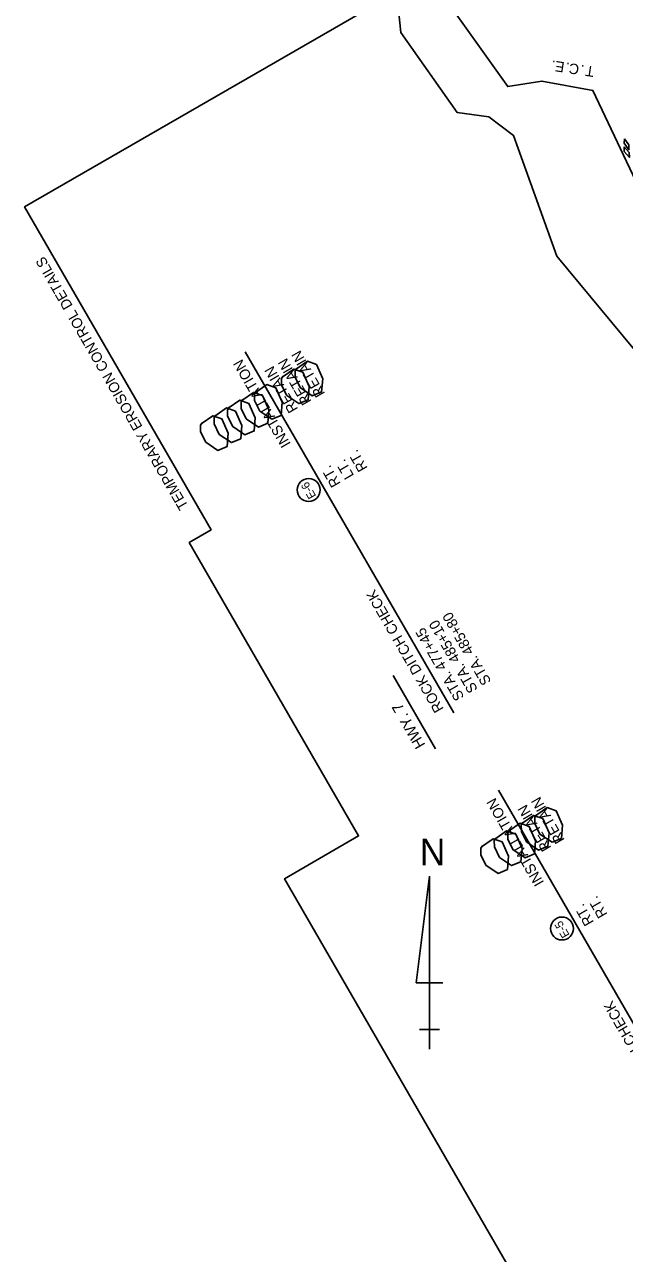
# Model space of a CAD drawing. Extents: x 956270 to 957915, y 1920520 to 1922423.
# Drawn here: x 956270 to 956617, y 1921329 to 1922039 of the extents above; entities that cross this region are included whole.
import ezdxf

# ---------------------------------------------------------------- set-up
doc = ezdxf.new("R2010")
doc.units = 0
for name, color, linetype in [('1', 7, 'Continuous'), ('44', 7, 'Continuous'), ('63', 7, 'Continuous'), ('G-ANNO-SYMB', 7, 'Continuous'), ('NO PLOT', 7, 'Continuous'), ('R_Draft', 7, 'Continuous'), ('S_TREE', 7, 'Continuous')]:
    doc.layers.add(name, color=color, linetype=linetype)

msp = doc.modelspace()

# ---------------------------------------------------------------- linework, layer by layer
at = {"layer": '1'}
for centre in [(956434.43, 1921770.52), (956580.77, 1921517.05)]:
    msp.add_circle(centre, 6.61, dxfattribs=at)
at = {"layer": '44'}
for p, q in [((956518.31, 1921641.7), (956397.8, 1921850.42)), ((956507.68, 1921620.92), (956483.26, 1921663.22)), ((956664.65, 1921388.23), (956544.14, 1921596.95))]:
    msp.add_line(p, q, dxfattribs=at)
at = {"layer": '63'}
for p, q in [((956504.2, 1921547.25), (956496.5, 1921485.71)), ((956504.2, 1921447.25), (956504.2, 1921547.25)), ((956504.2, 1921547.25), (956504.2, 1921470.33)), ((956496.5, 1921485.71), (956511.89, 1921485.71)), ((956504.2, 1921447.25), (956504.2, 1921470.33)), ((956504.2, 1921458.79), (956498.43, 1921458.79)), ((956498.43, 1921458.79), (956509.97, 1921458.79)), ((956504.2, 1921447.25), (956504.2, 1921458.79))]:
    msp.add_line(p, q, dxfattribs=at)
at = {"layer": 'G-ANNO-SYMB'}
for points in [[(956616.88, 1921973.43), (956616.74, 1921970.87), (956619.46, 1921967.19), (956619.44, 1921969.96)], [(956616.71, 1921968.75), (956616.77, 1921966.18), (956619.77, 1921962.73), (956619.54, 1921965.49)]]:
    msp.add_lwpolyline(points, close=True, dxfattribs=at)
at = {"layer": 'NO PLOT'}
msp.add_lwpolyline([(957012.51, 1920520.44), (956420.48, 1921545.87), (956463.26, 1921570.57), (956365.36, 1921740.14), (956378, 1921747.44), (956270.25, 1921934.07), (956666.17, 1922162.65), (956816.66, 1921901.98), (956749.98, 1921863.48), (956962.48, 1921495.42), (957029.16, 1921533.92), (957172.25, 1921286.08), (957120.9, 1921256.43), (957292.23, 1920959.68), (957343.58, 1920989.33), (957463.85, 1920781.02)], close=True, dxfattribs=at)
msp.add_lwpolyline([(957012.51, 1920520.44), (956420.48, 1921545.87), (956463.26, 1921570.57), (956365.36, 1921740.14), (956378, 1921747.44), (956270.25, 1921934.07), (956666.17, 1922162.65), (956816.66, 1921901.98), (956749.98, 1921863.48), (956962.48, 1921495.42), (957029.16, 1921533.92), (957172.25, 1921286.08), (957120.9, 1921256.43), (957292.23, 1920959.68), (957343.58, 1920989.33), (957463.85, 1920781.02)], close=True, dxfattribs=at)
msp.add_lwpolyline([(957012.51, 1920520.44), (956420.48, 1921545.87), (956463.26, 1921570.57), (956365.36, 1921740.14), (956378, 1921747.44), (956270.25, 1921934.07), (956666.17, 1922162.65), (956816.66, 1921901.98), (956749.98, 1921863.48), (956962.48, 1921495.42), (957029.16, 1921533.92), (957172.25, 1921286.08), (957120.9, 1921256.43), (957292.23, 1920959.68), (957343.58, 1920989.33), (957463.85, 1920781.02)], close=True, dxfattribs=at)
msp.add_lwpolyline([(957012.51, 1920520.44), (956420.48, 1921545.87), (956463.26, 1921570.57), (956365.36, 1921740.14), (956378, 1921747.44), (956270.25, 1921934.07), (956666.17, 1922162.65), (956816.66, 1921901.98), (956749.98, 1921863.48), (956962.48, 1921495.42), (957029.16, 1921533.92), (957172.25, 1921286.08), (957120.9, 1921256.43), (957292.23, 1920959.68), (957343.58, 1920989.33), (957463.85, 1920781.02)], close=True, dxfattribs=at)
msp.add_lwpolyline([(956978.43, 1921300.96), (956891.96, 1921416.34), (956761.21, 1921624.84), (956685.68, 1921817.75), (956598.64, 1922001.42), (956569.16, 1922006.84), (956549.42, 1922003.64), (956496.56, 1922078), (956484.6, 1922065.05), (956487.74, 1922034.93), (956520.15, 1921988.76), (956538.43, 1921986.13), (956552.84, 1921975.42), (956577.89, 1921905.71), (956667.63, 1921797.4), (956675.52, 1921785.98), (956734.33, 1921642.98), (956883.87, 1921386.21), (956963.43, 1921282.81)], dxfattribs=at)
at = {"layer": 'S_TREE'}
for points in [[(956426.89, 1921840.2), (956433.65, 1921844.93), (956438.88, 1921843.08), (956442.53, 1921834.76), (956441.9, 1921827.15), (956436.51, 1921824.91), (956429.5, 1921829.65), (956426.55, 1921835.67), (956426.52, 1921839.38), (956427.48, 1921840.79)], [(956426.89, 1921840.2), (956433.65, 1921844.93), (956438.88, 1921843.08), (956442.53, 1921834.76), (956441.9, 1921827.15), (956436.51, 1921824.91), (956429.5, 1921829.65), (956426.55, 1921835.67), (956426.52, 1921839.38), (956427.48, 1921840.79)], [(956426.89, 1921840.2), (956433.65, 1921844.93), (956438.88, 1921843.08), (956442.53, 1921834.76), (956441.9, 1921827.15), (956436.51, 1921824.91), (956429.5, 1921829.65), (956426.55, 1921835.67), (956426.52, 1921839.38), (956427.48, 1921840.79)], [(956426.89, 1921840.2), (956433.65, 1921844.93), (956438.88, 1921843.08), (956442.53, 1921834.76), (956441.9, 1921827.15), (956436.51, 1921824.91), (956429.5, 1921829.65), (956426.55, 1921835.67), (956426.52, 1921839.38), (956427.48, 1921840.79)], [(956426.89, 1921840.2), (956433.65, 1921844.93), (956438.88, 1921843.08), (956442.53, 1921834.76), (956441.9, 1921827.15), (956436.51, 1921824.91), (956429.5, 1921829.65), (956426.55, 1921835.67), (956426.52, 1921839.38), (956427.48, 1921840.79)], [(956419.1, 1921835.7), (956425.85, 1921840.43), (956431.08, 1921838.58), (956434.73, 1921830.26), (956434.11, 1921822.65), (956428.71, 1921820.41), (956421.7, 1921825.15), (956418.76, 1921831.17), (956418.72, 1921834.88), (956419.69, 1921836.29)], [(956419.1, 1921835.7), (956425.85, 1921840.43), (956431.08, 1921838.58), (956434.73, 1921830.26), (956434.11, 1921822.65), (956428.71, 1921820.41), (956421.7, 1921825.15), (956418.76, 1921831.17), (956418.72, 1921834.88), (956419.69, 1921836.29)], [(956419.1, 1921835.7), (956425.85, 1921840.43), (956431.08, 1921838.58), (956434.73, 1921830.26), (956434.11, 1921822.65), (956428.71, 1921820.41), (956421.7, 1921825.15), (956418.76, 1921831.17), (956418.72, 1921834.88), (956419.69, 1921836.29)], [(956403.51, 1921826.7), (956410.26, 1921831.43), (956415.49, 1921829.58), (956419.14, 1921821.26), (956418.52, 1921813.65), (956413.12, 1921811.41), (956406.11, 1921816.15), (956403.17, 1921822.17), (956403.14, 1921825.88), (956404.1, 1921827.29)], [(956403.51, 1921826.7), (956410.26, 1921831.43), (956415.49, 1921829.58), (956419.14, 1921821.26), (956418.52, 1921813.65), (956413.12, 1921811.41), (956406.11, 1921816.15), (956403.17, 1921822.17), (956403.14, 1921825.88), (956404.1, 1921827.29)], [(956403.51, 1921826.7), (956410.26, 1921831.43), (956415.49, 1921829.58), (956419.14, 1921821.26), (956418.52, 1921813.65), (956413.12, 1921811.41), (956406.11, 1921816.15), (956403.17, 1921822.17), (956403.14, 1921825.88), (956404.1, 1921827.29)], [(956403.51, 1921826.7), (956410.26, 1921831.43), (956415.49, 1921829.58), (956419.14, 1921821.26), (956418.52, 1921813.65), (956413.12, 1921811.41), (956406.11, 1921816.15), (956403.17, 1921822.17), (956403.14, 1921825.88), (956404.1, 1921827.29)], [(956403.51, 1921826.7), (956410.26, 1921831.43), (956415.49, 1921829.58), (956419.14, 1921821.26), (956418.52, 1921813.65), (956413.12, 1921811.41), (956406.11, 1921816.15), (956403.17, 1921822.17), (956403.14, 1921825.88), (956404.1, 1921827.29)], [(956387.92, 1921817.7), (956394.68, 1921822.43), (956399.91, 1921820.58), (956403.56, 1921812.26), (956402.93, 1921804.65), (956397.54, 1921802.41), (956390.53, 1921807.15), (956387.58, 1921813.17), (956387.55, 1921816.88), (956388.51, 1921818.29)], [(956387.92, 1921817.7), (956394.68, 1921822.43), (956399.91, 1921820.58), (956403.56, 1921812.26), (956402.93, 1921804.65), (956397.54, 1921802.41), (956390.53, 1921807.15), (956387.58, 1921813.17), (956387.55, 1921816.88), (956388.51, 1921818.29)], [(956387.92, 1921817.7), (956394.68, 1921822.43), (956399.91, 1921820.58), (956403.56, 1921812.26), (956402.93, 1921804.65), (956397.54, 1921802.41), (956390.53, 1921807.15), (956387.58, 1921813.17), (956387.55, 1921816.88), (956388.51, 1921818.29)], [(956395.72, 1921822.2), (956402.47, 1921826.93), (956407.7, 1921825.08), (956411.35, 1921816.76), (956410.73, 1921809.15), (956405.33, 1921806.91), (956398.32, 1921811.65), (956395.37, 1921817.67), (956395.34, 1921821.38), (956396.3, 1921822.79)], [(956395.72, 1921822.2), (956402.47, 1921826.93), (956407.7, 1921825.08), (956411.35, 1921816.76), (956410.73, 1921809.15), (956405.33, 1921806.91), (956398.32, 1921811.65), (956395.37, 1921817.67), (956395.34, 1921821.38), (956396.3, 1921822.79)], [(956395.72, 1921822.2), (956402.47, 1921826.93), (956407.7, 1921825.08), (956411.35, 1921816.76), (956410.73, 1921809.15), (956405.33, 1921806.91), (956398.32, 1921811.65), (956395.37, 1921817.67), (956395.34, 1921821.38), (956396.3, 1921822.79)], [(956395.72, 1921822.2), (956402.47, 1921826.93), (956407.7, 1921825.08), (956411.35, 1921816.76), (956410.73, 1921809.15), (956405.33, 1921806.91), (956398.32, 1921811.65), (956395.37, 1921817.67), (956395.34, 1921821.38), (956396.3, 1921822.79)], [(956380.13, 1921813.2), (956386.88, 1921817.93), (956392.11, 1921816.08), (956395.76, 1921807.76), (956395.14, 1921800.15), (956389.74, 1921797.91), (956382.73, 1921802.65), (956379.78, 1921808.67), (956379.75, 1921812.38), (956380.72, 1921813.79)], [(956372.33, 1921808.7), (956379.09, 1921813.43), (956384.32, 1921811.58), (956387.97, 1921803.26), (956387.34, 1921795.65), (956381.95, 1921793.41), (956374.94, 1921798.15), (956371.99, 1921804.17), (956371.96, 1921807.88), (956372.92, 1921809.29)], [(956557.65, 1921577.73), (956564.4, 1921582.46), (956569.63, 1921580.61), (956573.28, 1921572.29), (956572.66, 1921564.68), (956567.26, 1921562.44), (956560.25, 1921567.18), (956557.3, 1921573.2), (956557.27, 1921576.91), (956558.24, 1921578.32)], [(956565.44, 1921582.23), (956572.19, 1921586.96), (956577.42, 1921585.11), (956581.07, 1921576.79), (956580.45, 1921569.18), (956575.05, 1921566.94), (956568.05, 1921571.68), (956565.1, 1921577.7), (956565.07, 1921581.41), (956566.03, 1921582.82)], [(956542.06, 1921568.73), (956548.81, 1921573.46), (956554.04, 1921571.61), (956557.69, 1921563.29), (956557.07, 1921555.68), (956551.67, 1921553.44), (956544.66, 1921558.18), (956541.71, 1921564.2), (956541.68, 1921567.91), (956542.65, 1921569.32)], [(956542.06, 1921568.73), (956548.81, 1921573.46), (956554.04, 1921571.61), (956557.69, 1921563.29), (956557.07, 1921555.68), (956551.67, 1921553.44), (956544.66, 1921558.18), (956541.71, 1921564.2), (956541.68, 1921567.91), (956542.65, 1921569.32)], [(956542.06, 1921568.73), (956548.81, 1921573.46), (956554.04, 1921571.61), (956557.69, 1921563.29), (956557.07, 1921555.68), (956551.67, 1921553.44), (956544.66, 1921558.18), (956541.71, 1921564.2), (956541.68, 1921567.91), (956542.65, 1921569.32)], [(956549.85, 1921573.23), (956556.61, 1921577.96), (956561.84, 1921576.11), (956565.49, 1921567.79), (956564.86, 1921560.18), (956559.47, 1921557.94), (956552.46, 1921562.68), (956549.51, 1921568.7), (956549.48, 1921572.41), (956550.44, 1921573.82)], [(956549.85, 1921573.23), (956556.61, 1921577.96), (956561.84, 1921576.11), (956565.49, 1921567.79), (956564.86, 1921560.18), (956559.47, 1921557.94), (956552.46, 1921562.68), (956549.51, 1921568.7), (956549.48, 1921572.41), (956550.44, 1921573.82)], [(956549.85, 1921573.23), (956556.61, 1921577.96), (956561.84, 1921576.11), (956565.49, 1921567.79), (956564.86, 1921560.18), (956559.47, 1921557.94), (956552.46, 1921562.68), (956549.51, 1921568.7), (956549.48, 1921572.41), (956550.44, 1921573.82)], [(956549.85, 1921573.23), (956556.61, 1921577.96), (956561.84, 1921576.11), (956565.49, 1921567.79), (956564.86, 1921560.18), (956559.47, 1921557.94), (956552.46, 1921562.68), (956549.51, 1921568.7), (956549.48, 1921572.41), (956550.44, 1921573.82)], [(956549.85, 1921573.23), (956556.61, 1921577.96), (956561.84, 1921576.11), (956565.49, 1921567.79), (956564.86, 1921560.18), (956559.47, 1921557.94), (956552.46, 1921562.68), (956549.51, 1921568.7), (956549.48, 1921572.41), (956550.44, 1921573.82)], [(956534.26, 1921564.23), (956541.02, 1921568.96), (956546.25, 1921567.11), (956549.9, 1921558.79), (956549.27, 1921551.18), (956543.88, 1921548.94), (956536.87, 1921553.68), (956533.92, 1921559.7), (956533.89, 1921563.41), (956534.85, 1921564.82)], [(956534.26, 1921564.23), (956541.02, 1921568.96), (956546.25, 1921567.11), (956549.9, 1921558.79), (956549.27, 1921551.18), (956543.88, 1921548.94), (956536.87, 1921553.68), (956533.92, 1921559.7), (956533.89, 1921563.41), (956534.85, 1921564.82)]]:
    msp.add_lwpolyline(points, dxfattribs=at)

# ---------------------------------------------------------------- texts
at = {"layer": '1'}
for s, height, p in [('TEMPORARY EROSION CONTROL DETAILS', 6, (956365.12, 1921761.15)), ('E-6 ', 4.8, (956438.84, 1921767.07)), ('E-5 ', 4.8, (956585.33, 1921513.33))]:
    msp.add_text(s, height=height, rotation=120, dxfattribs=at).set_placement(p)
at = {"layer": '44'}
for s, height, p in [('RETAIN', 6, (956444.02, 1921826.24)), ('INSTALLATION', 6, (956424.23, 1921797.14)), ('RETAIN', 6, (956436.23, 1921821.74)), ('RETAIN', 6, (956428.43, 1921817.24)), ('RT.', 6, (956468.67, 1921783.21)), ('LT.', 6, (956460.81, 1921778.83)), ('RT.', 6, (956453.08, 1921774.21)), ('ROCK DITCH CHECK', 6, (956512.66, 1921643.98)), ('STA. 485+10', 6, (956532.29, 1921655.31)), ('STA. 485+80', 6, (956540.09, 1921659.81)), ('STA. 477+45', 6, (956524.5, 1921650.81)), ('HWY. 7', 6.25, (956501.98, 1921623.23)), ('INSTALLATION', 6, (956570.57, 1921543.67)), ('RETAIN', 6, (956574.77, 1921563.77)), ('RETAIN', 6, (956582.57, 1921568.27)), ('RT.', 6, (956599.43, 1921520.74)), ('RT.', 6, (956607.22, 1921525.24)), ('SAND BAG DITCH CHECK', 6, (956659, 1921390.5))]:
    msp.add_text(s, height=height, rotation=120, dxfattribs=at).set_placement(p)
at = {"layer": '63'}
msp.add_text('N', height=15.38, rotation=360, dxfattribs=at).set_placement((956498.56, 1921553.66))
at = {"layer": 'R_Draft'}
for s, p in [('.', (956577.24, 1922018.5)), ('E', (956582.56, 1922017.69)), ('.', (956585.46, 1922017.25)), ('C', (956591.06, 1922016.4)), ('.', (956593.96, 1922015.97)), ('T', (956599.75, 1922015.09))]:
    msp.add_text(s, height=6, rotation=171.38948, dxfattribs=at).set_placement(p)

doc.saveas('drawing.dxf')
